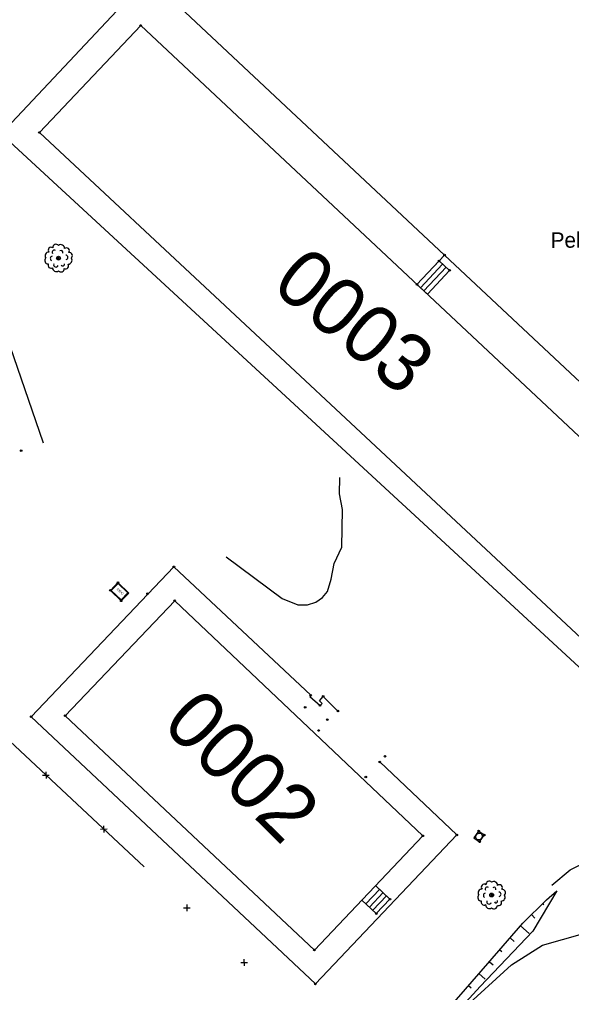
# Model space of a CAD drawing. Extents: x 344013 to 344423, y 298505 to 298795.
# Drawn here: x 344122.6 to 344157.5, y 298556.7 to 298618.3 of the extents above; entities that cross this region are included whole.
import ezdxf

# ---------------------------------------------------------------- set-up
doc = ezdxf.new("R2010")
doc.units = 0
for name, color, linetype in [('Default', 7, 'Continuous'), ('DH_CADRE -CARTOUCHE', 7, 'Continuous'), ('PC_CONCRETE', 7, 'Continuous'), ('PS_BOLT', 7, 'Continuous'), ('PS_CONST', 7, 'Continuous'), ('PS_DIM', 7, 'Continuous'), ('PS_WELD', 7, 'Continuous'), ('RES_ELECTRICITE', 7, 'Continuous'), ('TOPO_COURBE NIVEAU', 7, 'Continuous'), ('TOPO_POINT', 7, 'Continuous'), ('TOPO_TALUS-TERRAIN NATUREL', 7, 'Continuous'), ('VOIRIE_BORDURE', 7, 'Continuous'), ('VOIRIE_ESPACE VERT', 7, 'Continuous')]:
    doc.layers.add(name, color=color, linetype=linetype)

# ---------------------------------------------------------------- blocks, each defined once
blk = doc.blocks.new('REG_INC')
at = {"layer": 'Default'}
for p, q in [((0, 1), (1, 1)), ((0, 0), (0, 1)), ((1, 0), (0, 0)), ((1, 1), (1, 0))]:
    blk.add_line(p, q, dxfattribs=at)
for start, end in [(135.0055, 180.0055), (180.0066, 225.0066), (90.0058, 135.0058), (225.0069, 270.0069), (45.0069, 90.0069), (270.0058, 315.0058), (0.0066, 45.0066), (315.0055, 0.0055)]:
    blk.add_arc((0.5, 0.5), 0.44, start, end, dxfattribs=at)
blk = doc.blocks.new('RES_ELECTRICITE')
at = {"layer": 'RES_ELECTRICITE'}
for points in [[(0, 0), (0, 1), (1, 1), (1, 0)], [(0.05, 0.05), (0.05, 0.95), (0.95, 0.95), (0.95, 0.05)]]:
    blk.add_lwpolyline(points, close=True, dxfattribs=at)
blk.add_text('EEC', height=0.2, dxfattribs=at).set_placement((0.237, 0.46))
blk = doc.blocks.new('POINT_DISPLAY')
at = {"layer": 'Default'}
blk.add_circle((0, 0), 0.05, dxfattribs=at)
blk = doc.blocks.new('ARB1')
at = {"layer": 'Default'}
blk.add_circle((0, 0), 0.122, dxfattribs=at)
for centre, radius, start, end in [((-0.471, 0.503), 0.183, 53.95544, 222.20655), ((-0.153, 0.664), 0.211, 43.69255, 183.5969), ((0.139, 0.613), 0.241, 358.45835, 125.19284), ((0.501, 0.468), 0.183, 325.14445, 131.01755), ((-0.613, 0.139), 0.241, 88.45835, 215.19284), ((-0.373, -0.024), 0.149, 103.70924, 242.34652), ((-0.276, 0.37), 0.134, 52.43963, 209.54959), ((0.164, 0.38), 0.112, 330.58954, 133.71274), ((0.458, 0.052), 0.137, 276.62143, 88.96702), ((0.613, -0.139), 0.241, 268.45835, 35.19284), ((0.664, 0.153), 0.211, 313.69255, 93.5969), ((-0.664, -0.153), 0.211, 133.69255, 273.5969), ((-0.478, -0.443), 0.19, 155.22426, 300.93774), ((-0.139, -0.613), 0.241, 178.45835, 305.19284), ((-0.163, -0.42), 0.148, 159.53711, 338.16632), ((0.271, -0.38), 0.112, 210.58954, 13.71274), ((0.448, -0.483), 0.188, 243.13234, 33.02965), ((0.153, -0.664), 0.211, 223.69255, 3.5969)]:
    blk.add_arc(centre, radius, start, end, dxfattribs=at)

msp = doc.modelspace()

# ---------------------------------------------------------------- linework, layer by layer
at = {"layer": 'DH_CADRE -CARTOUCHE'}
for points in [[(344159.085, 298578.25), (344123.824, 298611.129), (344130.237, 298617.899), (344165.405, 298584.943)], [(344125.459, 298574.243), (344141.227, 298559.424), (344148.086, 298566.649), (344132.39, 298581.516)]]:
    msp.add_lwpolyline(points, close=True, dxfattribs=at)
at = {"layer": 'PC_CONCRETE'}
msp.add_lwpolyline([(344147.717, 298601.519), (344149.113, 298603.008), (344149.78, 298602.408), (344148.372, 298600.905)], close=True, dxfattribs=at)
for points in [[(344147.936, 298601.313), (344149.336, 298602.807)], [(344149.557, 298602.609), (344148.153, 298601.111)]]:
    msp.add_lwpolyline(points, dxfattribs=at)
at = {"layer": 'PS_BOLT'}
for points in [[(344173.444, 298593.641), (344172.427, 298592.568), (344178.462, 298586.939), (344174.396, 298582.587), (344168.376, 298588.228), (344167.085, 298586.853), (344168.386, 298585.586), (344159.324, 298576.069), (344121.411, 298611.054), (344130.716, 298620.945), (344149.461, 298603.379), (344147.717, 298601.519)], [(344149.461, 298603.379), (344166.011, 298587.87), (344172.356, 298594.641)], [(344145.36, 298571.324), (344150.236, 298566.706), (344141.289, 298557.281), (344123.303, 298574.184), (344132.335, 298583.661), (344140.996, 298575.54), (344140.93, 298575.464), (344141.582, 298574.891), (344141.725, 298575.026), (344141.55, 298575.188), (344141.782, 298575.465), (344142.714, 298574.538)]]:
    msp.add_lwpolyline(points, dxfattribs=at)
at = {"layer": 'PS_DIM'}
for points in [[(344144.233, 298562.591), (344145.138, 298561.732), (344146.003, 298562.643), (344145.099, 298563.502)], [(344144.486, 298562.351), (344145.351, 298563.263)], [(344144.703, 298562.145), (344145.568, 298563.056)], [(344144.921, 298561.938), (344145.786, 298562.85)]]:
    msp.add_lwpolyline(points, dxfattribs=at)
at = {"layer": 'PS_WELD'}
for p, q in [((344124.231, 298570.698), (344124.246, 298570.274)), ((344124.026, 298570.478), (344124.45, 298570.493)), ((344127.685, 298567.071), (344128.109, 298567.086)), ((344127.89, 298567.29), (344127.905, 298566.866)), ((344132.945, 298562.086), (344133.369, 298562.095)), ((344133.152, 298562.303), (344133.162, 298561.878)), ((344136.561, 298558.633), (344136.985, 298558.643)), ((344136.768, 298558.85), (344136.778, 298558.426))]:
    msp.add_line(p, q, dxfattribs=at)
msp.add_lwpolyline([(344066.325, 298620.987), (344067.282, 298617.46), (344068.599, 298614.563), (344074.052, 298608.813), (344088.412, 298595.164), (344102.784, 298581.36), (344108.792, 298575.318), (344111.119, 298574.7), (344113.481, 298575.53), (344116.239, 298577.918), (344119.964, 298574.466), (344130.452, 298564.699)], dxfattribs=at)
at = {"layer": 'TOPO_COURBE NIVEAU'}
for points in [[(344135.635, 298584.285), (344139.186, 298581.668), (344140.177, 298581.257), (344140.799, 298581.248), (344141.326, 298581.428), (344141.744, 298581.718), (344142.052, 298582.103), (344142.289, 298582.874), (344142.479, 298583.865), (344142.961, 298584.911), (344143.004, 298587.279), (344142.809, 298588.279), (344142.834, 298589.309)], [(344156.256, 298563.524), (344157.409, 298564.509), (344161.369, 298566.478), (344162.88, 298567.483), (344163.228, 298567.922), (344165.643, 298572.732), (344166.068, 298573.157), (344166.564, 298573.494), (344167.517, 298574.16), (344168.147, 298574.694), (344168.934, 298574.993), (344169.564, 298575.023), (344177.835, 298574.512)], [(344144.559, 298543.398), (344145.126, 298543.758), (344146.164, 298544.291), (344147.173, 298545.407), (344147.575, 298546.106), (344147.955, 298547.238), (344148.408, 298549.983), (344148.576, 298551.974), (344149.201, 298553.647), (344150.556, 298555.627), (344153.701, 298558.494), (344155.669, 298559.733), (344159.453, 298560.805), (344165.265, 298563.828)]]:
    msp.add_lwpolyline(points, dxfattribs=at)
at = {"layer": 'TOPO_TALUS-TERRAIN NATUREL'}
for p, q in [((344156.417, 298563.039), (344156.438, 298563.014)), ((344155.669, 298562.377), (344155.737, 298562.309)), ((344154.964, 298561.667), (344155.183, 298561.45)), ((344154.27, 298560.947), (344154.814, 298560.472)), ((344153.612, 298560.193), (344153.87, 298559.968)), ((344152.954, 298559.44), (344153.077, 298559.333)), ((344152.296, 298558.687), (344152.529, 298558.483)), ((344151.639, 298557.933), (344152.037, 298557.586)), ((344150.982, 298557.179), (344151.152, 298557.03))]:
    msp.add_line(p, q, dxfattribs=at)
for points in [[(344140.996, 298545.673), (344142.019, 298545.089), (344143.508, 298545.707), (344144.43, 298546.8), (344144.896, 298547.955), (344145.181, 298549.072), (344145.08, 298549.726), (344143.964, 298550.907), (344142.041, 298552.664), (344141.365, 298553.39), (344141.256, 298553.846), (344141.956, 298553.617), (344143.457, 298552.457), (344144.457, 298551.549), (344145.179, 298550.84), (344145.73, 298550.587), (344146.464, 298551.459), (344147.852, 298553.408), (344149.8, 298555.822), (344152.196, 298558.572), (344154.419, 298561.118), (344155.902, 298562.612), (344156.573, 298563.169)], [(344156.573, 298563.169), (344155.057, 298560.622), (344151.713, 298557.116), (344149.869, 298555.121), (344148.299, 298552.896), (344147.446, 298550.756), (344146.782, 298549.246), (344146.008, 298547.768), (344145.446, 298546.202), (344145.223, 298544.768), (344144.523, 298544.18), (344143.995, 298543.952), (344143.209, 298543.985), (344142.383, 298544.262), (344141.99, 298544.53), (344141.526, 298544.807), (344140.996, 298545.673)]]:
    msp.add_lwpolyline(points, dxfattribs=at)
at = {"layer": 'VOIRIE_BORDURE'}
msp.add_lwpolyline([(344124.087, 298591.493), (344119.864, 298603.699), (344116.2, 298614.781), (344116.04, 298616.133), (344116.105, 298617.106), (344116.408, 298618.318), (344117.143, 298619.443), (344117.987, 298620.373), (344118.918, 298621.174), (344120.412, 298621.951)], dxfattribs=at)

# ---------------------------------------------------------------- block references
at = {"layer": 'PC_CONCRETE', "xscale": 0.516732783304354, "yscale": -0.44873614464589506, "rotation": -124.32267000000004}
msp.add_blockref('REG_INC', (344151.974, 298566.694), dxfattribs=at)
at = {"layer": 'RES_ELECTRICITE', "xscale": 0.9524817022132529, "yscale": 0.6858001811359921, "rotation": -44.14338}
msp.add_blockref('RES_ELECTRICITE', (344128.317, 298582.175), dxfattribs=at)
at = {"layer": 'TOPO_POINT'}
for p in [(344130.237, 298617.899), (344123.824, 298611.129), (344149.461, 298603.379), (344125.037, 298603.184), (344149.113, 298603.008), (344149.78, 298602.408), (344147.717, 298601.519), (344122.67, 298591.003), (344132.335, 298583.661), (344128.793, 298582.668), (344128.317, 298582.175), (344130.664, 298581.964), (344129, 298581.511), (344132.39, 298581.516), (344140.996, 298575.54), (344141.782, 298575.465), (344140.642, 298574.781), (344141.582, 298574.891), (344142.714, 298574.538), (344123.303, 298574.184), (344125.459, 298574.243), (344142.039, 298574.001), (344141.502, 298573.309), (344145.36, 298571.324), (344145.689, 298571.68), (344144.477, 298570.368), (344151.613, 298566.961), (344148.086, 298566.649), (344150.236, 298566.706), (344151.974, 298566.694), (344151.682, 298566.267), (344146.003, 298562.643), (344152.438, 298562.903), (344145.138, 298561.732), (344141.227, 298559.424), (344141.289, 298557.281)]:
    msp.add_blockref('POINT_DISPLAY', p, dxfattribs=at)
at = {"layer": 'VOIRIE_ESPACE VERT'}
for p in [(344125.037, 298603.184), (344152.438, 298562.903)]:
    msp.add_blockref('ARB1', p, dxfattribs=at)

# ---------------------------------------------------------------- texts
at = {"layer": 'PS_CONST'}
for s, height, rotation, p in [('Pelouse', 0.9758, 0.36653, (344156.182, 298603.834)), ('0003', 3.662, 320.36653, (344138.412, 298601.304)), ('0002', 3.662, 315.36654, (344131.489, 298573.614))]:
    msp.add_text(s, height=height, rotation=rotation, dxfattribs=at).set_placement(p)

doc.saveas('drawing.dxf')
